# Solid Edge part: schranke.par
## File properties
Author: Wir
Template: Normal.par
Last saved by: Wir
Revision: 2
Application: Solid Edge
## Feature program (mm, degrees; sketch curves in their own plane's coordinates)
sketch for "unnamed Protrusion 1" plane through (0, 0, 0) normal (0, 0, 1) x-axis (1, 0, 0)
extrude "unnamed Protrusion 1" add finite 10 symmetric
sketch for "unnamed Cutout 1" plane through (0, -2.5, 0) normal (0, -1, 0) x-axis (1, 0, 0)
extrude "unnamed Cutout 1" cut finite 44.45 symmetric
sketch for "unnamed Protrusion 2" plane through (0, 0, 0) normal (0, 0, 1) x-axis (1, 0, 0)
  circle centre (75, 0) radius 10
extrude "unnamed Protrusion 2" add finite 20 symmetric
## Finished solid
Body 1: solid body, 12 faces, 26 edges, 16 vertices.
  Faces by surface: plane 11, cylinder 1
  Edges by curve: line 22, circle 4
Bounding box of the edges (mm): 160.000 x 20.000 x 20.000, from (-75, -10, -10) to (85, 10, 10).
Cylindrical faces by radius (mm): R10 x1
Planar faces by outward normal: +x 1, +y 1, +z 3, -x 2, -y 1, -z 3
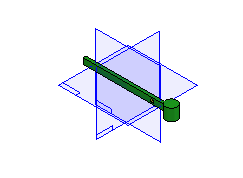
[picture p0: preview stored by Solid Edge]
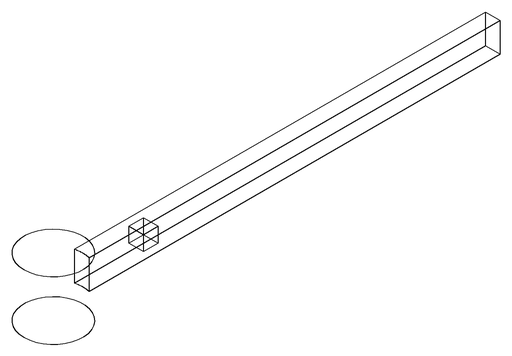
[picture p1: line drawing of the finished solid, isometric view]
